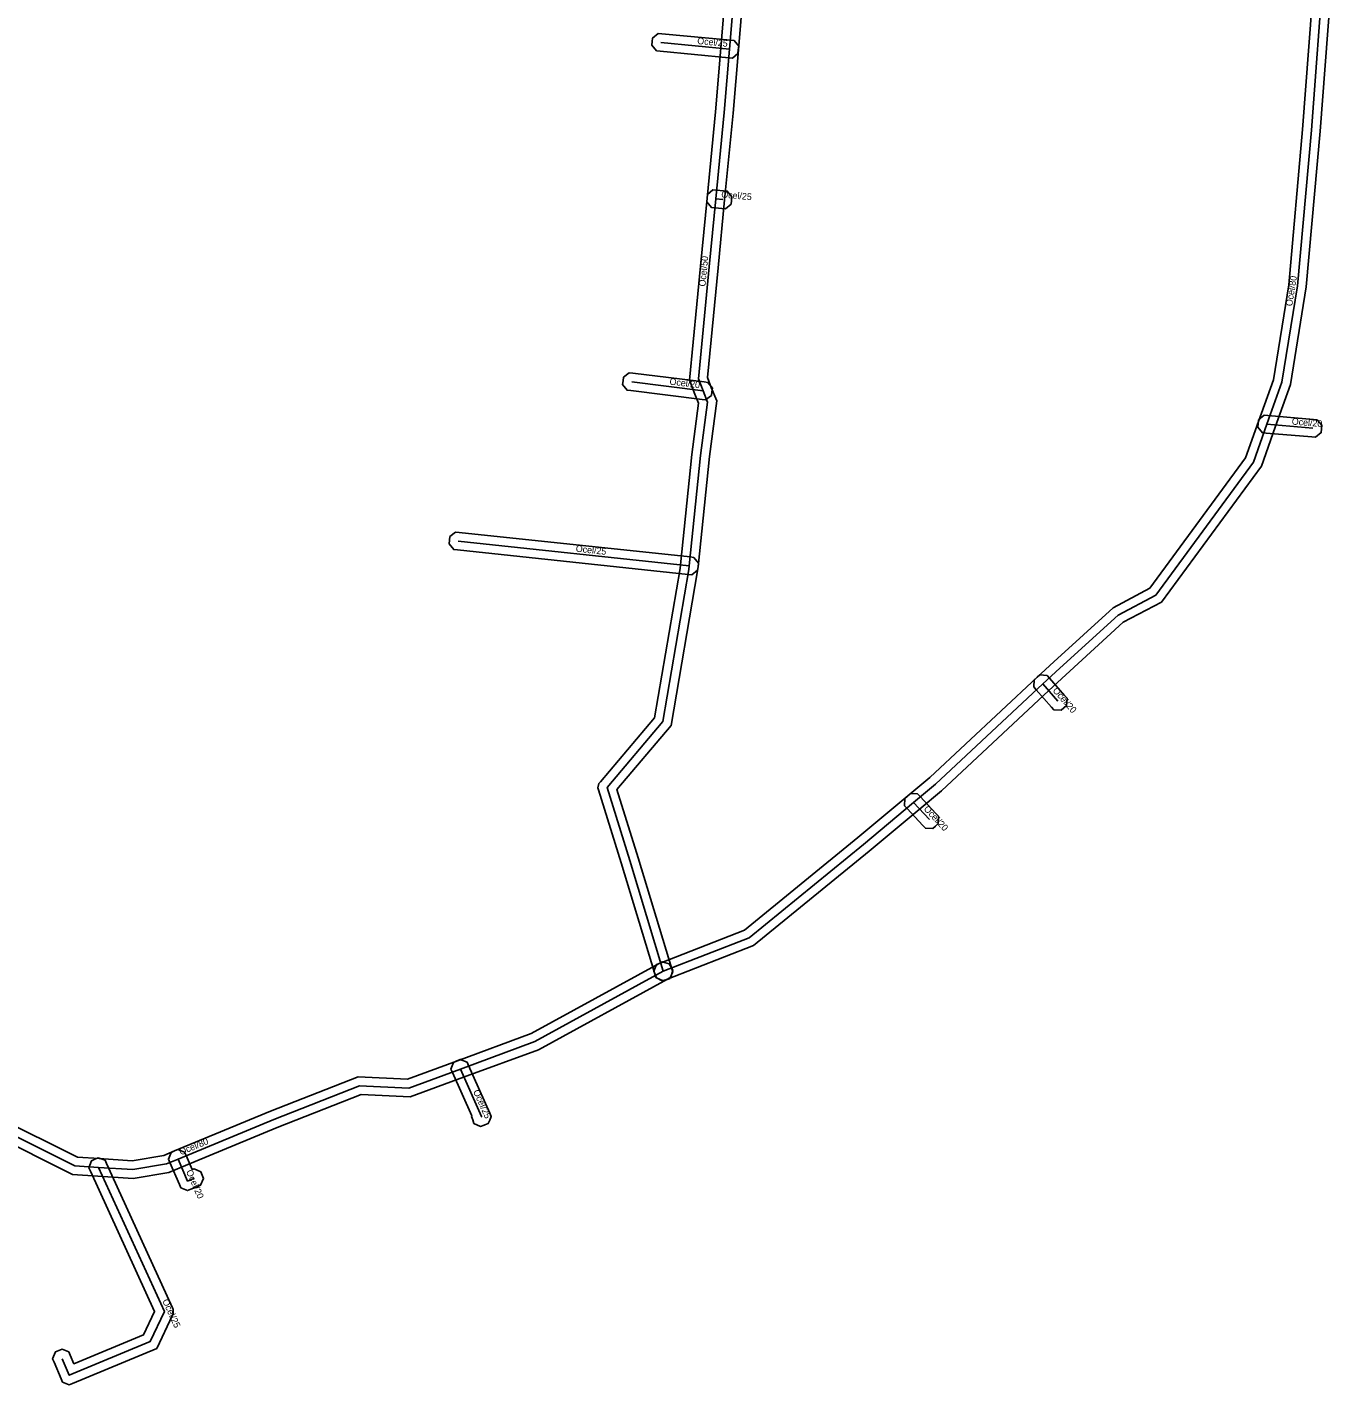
# Model space of a CAD drawing. Extents: x -569373 to -565022, y -1135090 to -1131496.
# Drawn here: x -566241.6 to -566092.5, y -1133998.1 to -1133844.4 of the extents above; entities that cross this region are included whole.
import ezdxf

# ---------------------------------------------------------------- set-up
doc = ezdxf.new("R2010")
doc.units = 0
for name, color, linetype in [('1', 7, 'Continuous'), ('24', 7, 'Continuous'), ('30', 7, 'Continuous')]:
    doc.layers.add(name, color=color, linetype=linetype)

msp = doc.modelspace()

# ---------------------------------------------------------------- linework, layer by layer
at = {"layer": '1'}
for points in [[(-566159.373, -1133825.833), (-566161.133, -1133846.943), (-566161.734, -1133854.13), (-566162.685, -1133863.927), (-566163.435, -1133871.627), (-566164.641, -1133884.053), (-566164.192, -1133885.168), (-566163.585, -1133886.691), (-566164.407, -1133892.996), (-566165.696, -1133905.458), (-566165.75, -1133905.931), (-566168.74, -1133923.428), (-566174.872, -1133930.668), (-566172.474, -1133938.407), (-566168.673, -1133950.97), (-566168.553, -1133951.367), (-566168.944, -1133952.097), (-566169.34, -1133952.217), (-566169.737, -1133952.337), (-566170.467, -1133951.946), (-566170.587, -1133951.55), (-566174.386, -1133938.993), (-566176.945, -1133930.736), (-566177.021, -1133930.491), (-566176.919, -1133929.989), (-566176.753, -1133929.794), (-566170.62, -1133922.552), (-566167.73, -1133905.649), (-566167.684, -1133905.242), (-566166.393, -1133892.764), (-566165.635, -1133886.949), (-566166.048, -1133885.912), (-566166.679, -1133884.347), (-566165.425, -1133871.433), (-566164.675, -1133863.733), (-566163.726, -1133853.95), (-566163.127, -1133846.777), (-566161.367, -1133825.667)], [(-566093.843, -1133837.286), (-566095.273, -1133856.142), (-566096.847, -1133873.794), (-566098.627, -1133884.82), (-566100.358, -1133889.675), (-566101.927, -1133894.094), (-566113.22, -1133909.457), (-566117.56, -1133911.755), (-566124.072, -1133917.685), (-566125.978, -1133919.461), (-566138.148, -1133930.83), (-566140.659, -1133932.928), (-566146.343, -1133937.661), (-566159.409, -1133948.354), (-566169.267, -1133952.192), (-566169.653, -1133952.342), (-566170.412, -1133952.009), (-566170.562, -1133951.623), (-566170.712, -1133951.237), (-566170.379, -1133950.478), (-566169.993, -1133950.328), (-566160.431, -1133946.606), (-566147.617, -1133936.119), (-566141.941, -1133931.392), (-566139.472, -1133929.33), (-566127.342, -1133917.999), (-566125.428, -1133916.215), (-566118.72, -1133910.105), (-566114.56, -1133907.903), (-566103.713, -1133893.146), (-566102.242, -1133889.005), (-566100.573, -1133884.32), (-566098.833, -1133873.546), (-566097.267, -1133855.978), (-566095.837, -1133837.134)], [(-566245.003, -1133967.791), (-566235.954, -1133972.286), (-566233.493, -1133972.452), (-566229.741, -1133972.704), (-566226.16, -1133972.093), (-566224.944, -1133971.587), (-566214.094, -1133967.092), (-566204.166, -1133963.201), (-566198.595, -1133963.462), (-566192.935, -1133961.381), (-566184.575, -1133958.307), (-566170.11, -1133950.383), (-566169.747, -1133950.184), (-566168.952, -1133950.417), (-566168.753, -1133950.78), (-566168.554, -1133951.143), (-566168.787, -1133951.938), (-566169.15, -1133952.137), (-566183.745, -1133960.133), (-566192.245, -1133963.259), (-566198.285, -1133965.478), (-566203.834, -1133965.219), (-566213.346, -1133968.948), (-566224.176, -1133973.433), (-566225.6, -1133974.027), (-566229.639, -1133974.716), (-566233.627, -1133974.448), (-566236.486, -1133974.254), (-566245.637, -1133969.709)]]:
    msp.add_lwpolyline(points, dxfattribs=at)
for points in [[(-566170.208, -1133845.086), (-566169.795, -1133845.125), (-566162.035, -1133845.865), (-566161.623, -1133845.904), (-566161.096, -1133846.542), (-566161.135, -1133846.955), (-566161.174, -1133847.367), (-566161.812, -1133847.894), (-566162.225, -1133847.855), (-566169.985, -1133847.115), (-566170.397, -1133847.076), (-566170.924, -1133846.438), (-566170.885, -1133846.025), (-566170.846, -1133845.613)], [(-566164.004, -1133862.797), (-566163.591, -1133862.834), (-566162.811, -1133862.904), (-566162.398, -1133862.941), (-566161.867, -1133863.576), (-566161.904, -1133863.989), (-566161.941, -1133864.402), (-566162.576, -1133864.933), (-566162.989, -1133864.896), (-566163.769, -1133864.826), (-566164.182, -1133864.789), (-566164.713, -1133864.154), (-566164.676, -1133863.741), (-566164.639, -1133863.328)], [(-566173.478, -1133883.497), (-566173.067, -1133883.548), (-566164.997, -1133884.548), (-566164.586, -1133884.599), (-566164.077, -1133885.252), (-566164.128, -1133885.663), (-566164.179, -1133886.074), (-566164.832, -1133886.583), (-566165.243, -1133886.532), (-566173.313, -1133885.532), (-566173.724, -1133885.481), (-566174.233, -1133884.828), (-566174.182, -1133884.417), (-566174.131, -1133884.006)], [(-566095.792, -1133890.811), (-566096.205, -1133890.776), (-566101.385, -1133890.336), (-566101.798, -1133890.301), (-566102.331, -1133889.668), (-566102.296, -1133889.255), (-566102.261, -1133888.842), (-566101.628, -1133888.309), (-566101.215, -1133888.344), (-566096.035, -1133888.784), (-566095.622, -1133888.819), (-566095.089, -1133889.452), (-566095.124, -1133889.865), (-566095.159, -1133890.278)], [(-566193.136, -1133901.532), (-566192.724, -1133901.576), (-566166.584, -1133904.356), (-566166.172, -1133904.399), (-566165.652, -1133905.044), (-566165.696, -1133905.456), (-566165.739, -1133905.868), (-566166.384, -1133906.388), (-566166.796, -1133906.344), (-566192.936, -1133903.564), (-566193.348, -1133903.521), (-566193.868, -1133902.876), (-566193.824, -1133902.464), (-566193.781, -1133902.052)], [(-566126.179, -1133917.761), (-566125.906, -1133918.073), (-566124.196, -1133920.033), (-566123.924, -1133920.345), (-566123.981, -1133921.171), (-566124.293, -1133921.444), (-566124.605, -1133921.716), (-566125.431, -1133921.659), (-566125.704, -1133921.347), (-566127.414, -1133919.387), (-566127.686, -1133919.075), (-566127.629, -1133918.249), (-566127.317, -1133917.976), (-566127.005, -1133917.704)], [(-566140.849, -1133931.176), (-566140.567, -1133931.48), (-566138.777, -1133933.41), (-566138.495, -1133933.714), (-566138.526, -1133934.541), (-566138.83, -1133934.823), (-566139.134, -1133935.105), (-566139.961, -1133935.074), (-566140.243, -1133934.77), (-566142.033, -1133932.84), (-566142.315, -1133932.536), (-566142.284, -1133931.709), (-566141.98, -1133931.427), (-566141.676, -1133931.145)], [(-566191.351, -1133967.703), (-566191.319, -1133967.633), (-566193.504, -1133962.727), (-566193.672, -1133962.348), (-566193.375, -1133961.575), (-566192.997, -1133961.406), (-566192.618, -1133961.238), (-566191.845, -1133961.535), (-566191.676, -1133961.913), (-566189.276, -1133967.303), (-566189.101, -1133967.698), (-566189.268, -1133968.096), (-566189.434, -1133968.495), (-566189.839, -1133968.646), (-566189.919, -1133968.676), (-566190.307, -1133968.821), (-566191.061, -1133968.479), (-566191.206, -1133968.091)], [(-566236.912, -1133994.337), (-566236.75, -1133994.718), (-566236.339, -1133995.685), (-566228.449, -1133992.395), (-566227.203, -1133989.763), (-566234.469, -1133973.866), (-566234.641, -1133973.489), (-566234.353, -1133972.713), (-566233.976, -1133972.541), (-566233.599, -1133972.369), (-566232.823, -1133972.657), (-566232.651, -1133973.034), (-566225.191, -1133989.354), (-566225.099, -1133989.555), (-566225.101, -1133989.998), (-566225.196, -1133990.198), (-566226.971, -1133993.945), (-566236.485, -1133997.913), (-566236.865, -1133998.072), (-566237.629, -1133997.761), (-566237.79, -1133997.382), (-566238.59, -1133995.502), (-566238.752, -1133995.121), (-566238.443, -1133994.352), (-566238.062, -1133994.19), (-566237.681, -1133994.028)], [(-566223.643, -1133972.112), (-566222.948, -1133973.713), (-566222.734, -1133973.628), (-566221.974, -1133973.956), (-566221.821, -1133974.341), (-566221.668, -1133974.726), (-566221.996, -1133975.486), (-566222.381, -1133975.639), (-566223.111, -1133975.929), (-566223.488, -1133976.079), (-566224.236, -1133975.77), (-566224.397, -1133975.398), (-566225.477, -1133972.908), (-566225.642, -1133972.528), (-566225.338, -1133971.757), (-566224.958, -1133971.593), (-566224.578, -1133971.428), (-566223.807, -1133971.732)]]:
    msp.add_lwpolyline(points, close=True, dxfattribs=at)
at = {"layer": '24'}
for points in [[(-566102.18, -1133776.33), (-566103.3, -1133787.99), (-566104.42, -1133798.34), (-566105.46, -1133807.95), (-566095.85, -1133815.05), (-566092.48, -1133816.21), (-566094.08, -1133824.95), (-566094.5, -1133832.8), (-566094.84, -1133837.21), (-566096.27, -1133856.06), (-566097.84, -1133873.67), (-566099.6, -1133884.57), (-566101.3, -1133889.34), (-566102.82, -1133893.62), (-566113.89, -1133908.68), (-566118.14, -1133910.93), (-566124.75, -1133916.95), (-566126.66, -1133918.73), (-566138.81, -1133930.08), (-566141.3, -1133932.16), (-566146.98, -1133936.89), (-566159.92, -1133947.48), (-566169.63, -1133951.26)], [(-566169.63, -1133951.26), (-566173.43, -1133938.7), (-566175.99, -1133930.44), (-566169.68, -1133922.99), (-566166.74, -1133905.79), (-566166.69, -1133905.35), (-566165.4, -1133892.88), (-566164.61, -1133886.82), (-566165.12, -1133885.54), (-566165.66, -1133884.2), (-566164.43, -1133871.53), (-566163.68, -1133863.83), (-566162.73, -1133854.04), (-566162.13, -1133846.86), (-566160.37, -1133825.75), (-566159.57, -1133816.19), (-566158.79, -1133807.17), (-566157.59, -1133793.2)], [(-566169.89, -1133846.12), (-566162.13, -1133846.86)], [(-566163.68, -1133863.83), (-566162.9, -1133863.9)], [(-566173.19, -1133884.54), (-566165.12, -1133885.54)], [(-566096.12, -1133889.78), (-566101.3, -1133889.34)], [(-566192.83, -1133902.57), (-566166.69, -1133905.35)], [(-566126.66, -1133918.73), (-566124.95, -1133920.69)], [(-566141.3, -1133932.16), (-566139.51, -1133934.09)], [(-566169.63, -1133951.26), (-566184.16, -1133959.22), (-566192.59, -1133962.32), (-566198.44, -1133964.47), (-566204, -1133964.21), (-566213.72, -1133968.02), (-566224.56, -1133972.51), (-566225.88, -1133973.06), (-566229.69, -1133973.71), (-566233.56, -1133973.45), (-566236.22, -1133973.27), (-566245.32, -1133968.75), (-566257.76, -1133966.52), (-566264.08, -1133964.81), (-566274.81, -1133959.56), (-566279.23, -1133956.91)], [(-566190.27, -1133967.74), (-566190.19, -1133967.71), (-566192.59, -1133962.32)], [(-566222.75, -1133974.71), (-566223.48, -1133975), (-566224.56, -1133972.51)], [(-566237.67, -1133995.11), (-566236.87, -1133996.99), (-566227.71, -1133993.17), (-566226.1, -1133989.77), (-566233.56, -1133973.45)]]:
    msp.add_lwpolyline(points, dxfattribs=at)

# ---------------------------------------------------------------- texts
at = {"layer": '30'}
for s, rotation, p in [('Ocel/25', 354.5527, (-566165.81, -1133846.29)), ('Ocel/25', 354.87181, (-566163.09, -1133863.665)), ('Ocel/50', 84.45512, (-566164.867, -1133873.767)), ('Ocel/80', 80.82774, (-566098.45, -1133876.01)), ('Ocel/20', 352.93616, (-566168.955, -1133884.84)), ('Ocel/20', 355.14483, (-566098.51, -1133889.36)), ('Ocel/25', 353.92939, (-566179.56, -1133903.76)), ('Ocel/20', 311.10304, (-566125.605, -1133919.51)), ('Ocel/20', 312.84472, (-566140.205, -1133932.925)), ('Ocel/25', 294.00193, (-566191.173, -1133964.854)), ('Ocel/80', 22.49966, (-566224.235, -1133972.093)), ('Ocel/20', 293.44806, (-566223.664, -1133973.915)), ('Ocel/25', 294.56551, (-566226.36, -1133988.563))]:
    msp.add_text(s, height=0.75, rotation=rotation, dxfattribs=at).set_placement(p)

doc.saveas('drawing.dxf')
